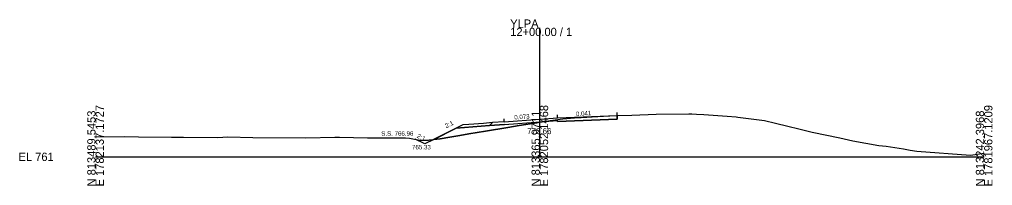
# Model space of a CAD drawing. Extents: x -76 to 1303, y -10 to 9544.
# Drawn here: x -25.7 to 302.8, y 1990.3 to 2046.4 of the extents above; entities that cross this region are included whole.
import ezdxf

# ---------------------------------------------------------------- set-up
doc = ezdxf.new("R2010")
doc.units = 0
for name, color, linetype in [('Exist Cross Section Cell', 7, 'Continuous'), ('Exist XS Center Line Elevation Label', 7, 'Continuous'), ('Exist XS Ground Line', 7, 'Continuous'), ('Prop XS Ditch Standard Text', 7, 'Continuous'), ('Prop XS Dump Level', 7, 'Continuous'), ('Prop XS Earthwork Shape', 7, 'Continuous'), ('Prop XS EOT Tick Mark', 7, 'Continuous'), ('Prop XS Finish Grade', 7, 'Continuous'), ('Prop XS Finish Grade Earthwork', 7, 'Continuous'), ('Prop XS Finish Grade Paved Shoulder', 7, 'Continuous'), ('Prop XS Finish Grade Pavement', 7, 'Continuous'), ('Prop XS Pvmt Edge Slope', 7, 'Continuous'), ('Prop XS SE Text', 7, 'Continuous'), ('Prop XS Side Slope Text', 7, 'Continuous'), ('Prop XS SS Elevation Text', 7, 'Continuous'), ('Prop XS Subgrade Earthwork', 7, 'Continuous'), ('Scratch_Level_3', 7, 'Continuous')]:
    doc.layers.add(name, color=color, linetype=linetype)

msp = doc.modelspace()

# ---------------------------------------------------------------- linework, layer by layer
at = {"layer": 'Exist Cross Section Cell'}
for p, q in [((150, 2000), (150, 2043.56)), ((0, 2000), (150, 2000)), ((150, 2000), (300, 2000))]:
    msp.add_line(p, q, dxfattribs=at)
at = {"layer": 'Exist XS Ground Line'}
for p, q in [((173.65, 2013.83), (176.08, 2013.96)), ((176.08, 2013.96), (181.09, 2014.1)), ((181.09, 2014.1), (189.28, 2014.34)), ((189.28, 2014.34), (200.26, 2014.5)), ((200.26, 2014.5), (201.27, 2014.52)), ((201.27, 2014.52), (202.84, 2014.45)), ((202.84, 2014.45), (205.32, 2014.33)), ((205.32, 2014.33), (213.24, 2013.69)), ((142.97, 2010.56), (148.94, 2011.49)), ((148.94, 2011.49), (150, 2011.66)), ((150, 2011.66), (152.31, 2012.03)), ((152.31, 2012.03), (153.48, 2012.22)), ((153.48, 2012.22), (157.72, 2012.87)), ((157.72, 2012.87), (163.07, 2013.23)), ((163.07, 2013.23), (163.57, 2013.26)), ((163.57, 2013.26), (163.9, 2013.28)), ((163.9, 2013.28), (171.51, 2013.71)), ((171.51, 2013.71), (173.65, 2013.83)), ((213.24, 2013.69), (216.27, 2013.45)), ((216.27, 2013.45), (216.86, 2013.38)), ((216.86, 2013.38), (225.85, 2012.21)), ((225.85, 2012.21), (229.61, 2011.35)), ((229.61, 2011.35), (233.76, 2010.39)), ((122.98, 2007.22), (126.08, 2007.73)), ((126.08, 2007.73), (131.62, 2008.67)), ((131.62, 2008.67), (139.21, 2009.93)), ((139.21, 2009.93), (142.97, 2010.56)), ((233.76, 2010.39), (237.42, 2009.46)), ((237.42, 2009.46), (241.89, 2008.34)), ((241.89, 2008.34), (251.3, 2006.46)), ((0, 2006.7), (9.62, 2006.88)), ((9.62, 2006.88), (14.55, 2006.79)), ((14.55, 2006.79), (25.68, 2006.66)), ((25.68, 2006.66), (28.17, 2006.67)), ((28.17, 2006.67), (29.73, 2006.67)), ((29.73, 2006.67), (41.31, 2006.56)), ((41.31, 2006.56), (44.67, 2006.76)), ((44.67, 2006.76), (53.07, 2006.53)), ((53.07, 2006.53), (70.95, 2006.44)), ((70.95, 2006.44), (80.75, 2006.6)), ((80.75, 2006.6), (82.37, 2006.59)), ((82.37, 2006.59), (91.82, 2006.43)), ((91.82, 2006.43), (102.93, 2006.39)), ((102.93, 2006.39), (104.6, 2006.41)), ((104.6, 2006.41), (106.03, 2006.34)), ((106.03, 2006.34), (109.36, 2005.67)), ((109.36, 2005.67), (110.87, 2005.58)), ((110.87, 2005.58), (112.38, 2005.57)), ((112.38, 2005.57), (112.8, 2005.72)), ((112.8, 2005.72), (114.2, 2005.85)), ((114.2, 2005.85), (116.32, 2006.11)), ((116.32, 2006.11), (119.66, 2006.67)), ((119.66, 2006.67), (122.98, 2007.22)), ((251.3, 2006.46), (255.67, 2005.43)), ((255.67, 2005.43), (264.5, 2003.87)), ((264.5, 2003.87), (266.93, 2003.56)), ((266.93, 2003.56), (272.78, 2002.65)), ((272.78, 2002.65), (275.01, 2002.29)), ((275.01, 2002.29), (277.27, 2001.92)), ((277.27, 2001.92), (295.36, 2000.57)), ((295.36, 2000.57), (300, 2001.25))]:
    msp.add_line(p, q, dxfattribs=at)
at = {"layer": 'Prop XS Dump Level'}
for p, q in [((138, 2011.83), (150, 2012.7)), ((150, 2012.7), (156, 2013.14))]:
    msp.add_line(p, q, dxfattribs=at)
at = {"layer": 'Prop XS Earthwork Shape'}
for points in [[(176.08, 2013.96), (176.1, 2013.96), (176.1, 2012.71), (156, 2011.88), (156, 2012.22), (151.35, 2011.88), (152.31, 2012.03), (153.48, 2012.22), (157.72, 2012.87), (163.07, 2013.23), (163.57, 2013.26), (163.9, 2013.28), (171.51, 2013.71), (173.65, 2013.83)], [(138.07, 2010.91), (150.07, 2011.79), (151.35, 2011.88), (150, 2011.66), (148.94, 2011.49), (142.97, 2010.56), (139.21, 2009.93), (131.62, 2008.67), (126.08, 2007.73), (122.98, 2007.22), (119.66, 2006.67), (116.32, 2006.11), (114.2, 2005.85), (121.8, 2009.65), (133.01, 2010.54)], [(114.2, 2005.85), (111.17, 2004.33), (107.91, 2005.96), (109.36, 2005.67), (110.87, 2005.58), (112.38, 2005.57), (112.8, 2005.72)]]:
    msp.add_lwpolyline(points, close=True, dxfattribs=at)
at = {"layer": 'Prop XS EOT Tick Mark'}
for p, q in [((156, 2013.14), (156, 2014.14)), ((176.1, 2013.96), (176.1, 2014.96)), ((138, 2011.83), (138, 2012.83))]:
    msp.add_line(p, q, dxfattribs=at)
at = {"layer": 'Prop XS Finish Grade'}
for p, q in [((124, 2010.75), (121.8, 2009.65)), ((126, 2010.9), (124, 2010.75)), ((131, 2011.3), (126, 2010.9)), ((134, 2011.54), (131, 2011.3))]:
    msp.add_line(p, q, dxfattribs=at)
at = {"layer": 'Prop XS Finish Grade Earthwork'}
for p, q in [((121.8, 2009.65), (111.17, 2004.33)), ((111.17, 2004.33), (107.91, 2005.96))]:
    msp.add_line(p, q, dxfattribs=at)
at = {"layer": 'Prop XS Finish Grade Paved Shoulder'}
for p, q in [((156, 2013.14), (176.1, 2013.96)), ((138, 2011.83), (134, 2011.54))]:
    msp.add_line(p, q, dxfattribs=at)
at = {"layer": 'Prop XS Finish Grade Pavement'}
for p, q in [((138, 2011.83), (150, 2012.7)), ((150, 2012.7), (156, 2013.14))]:
    msp.add_line(p, q, dxfattribs=at)
at = {"layer": 'Prop XS Pvmt Edge Slope'}
msp.add_line((134, 2011.54), (133.01, 2010.54), dxfattribs=at)
at = {"layer": 'Prop XS Subgrade Earthwork'}
for p, q in [((176.1, 2012.71), (176.1, 2013.96)), ((138.07, 2010.91), (133.01, 2010.54)), ((138.07, 2010.91), (150.07, 2011.79)), ((150.07, 2011.79), (156, 2012.22)), ((156, 2011.88), (176.1, 2012.71)), ((156, 2011.88), (156, 2012.22)), ((133.01, 2010.54), (121.8, 2009.65))]:
    msp.add_line(p, q, dxfattribs=at)
at = {"layer": 'Scratch_Level_3'}
for p, q in [((124, 2010.75), (121.8, 2009.65)), ((126, 2010.9), (124, 2010.75)), ((131, 2011.3), (126, 2010.9)), ((134, 2011.54), (131, 2011.3)), ((133.01, 2010.54), (134, 2011.54)), ((121.8, 2009.65), (133.01, 2010.54))]:
    msp.add_line(p, q, dxfattribs=at)

# ---------------------------------------------------------------- texts
at = {"layer": 'Exist Cross Section Cell'}
for s, p in [('YLPA', (140, 2043.56)), ('12+00.00 / 1', (140, 2040.76)), ('EL 761', (-26, 1998.6))]:
    msp.add_text(s, height=2.8, dxfattribs=at).set_placement(p)
for s, p in [('E 1782137.1727', (2.8, 1990)), ('E 1782052.1468', (152.8, 1990)), ('E 1781967.1209', (302.8, 1990)), ('N 813489.5453', (0, 1990)), ('N 813365.9711', (150, 1990)), ('N 813242.3968', (300, 1990))]:
    msp.add_text(s, height=2.8, rotation=90, dxfattribs=at).set_placement(p)
at = {"layer": 'Exist XS Center Line Elevation Label'}
msp.add_text('772.66', height=2, dxfattribs=at).set_placement((145.73, 2007.66))
at = {"layer": 'Prop XS Ditch Standard Text'}
msp.add_text('765.33', height=1.5, dxfattribs=at).set_placement((106.85, 2002.51))
at = {"layer": 'Prop XS Dump Level'}
msp.add_text('Case4', height=0.04, dxfattribs=at).set_placement((126, 2010.86))
at = {"layer": 'Prop XS SE Text'}
for s, rotation, p in [('0.073', 4.1601, (141.42, 2012.58)), ('0.041', 4.16, (162.25, 2013.7))]:
    msp.add_text(s, height=1.5, rotation=rotation, dxfattribs=at).set_placement(p)
at = {"layer": 'Prop XS Side Slope Text'}
for rotation, p in [(26.5651, (118.43, 2009.64)), (333.4349, (108.35, 2006.55))]:
    msp.add_text('2:1', height=1.5, rotation=rotation, dxfattribs=at).set_placement(p)
at = {"layer": 'Prop XS SS Elevation Text'}
msp.add_text('S.S. 766.96', height=1.5, dxfattribs=at).set_placement((96.47, 2007.1))

doc.saveas('drawing.dxf')
